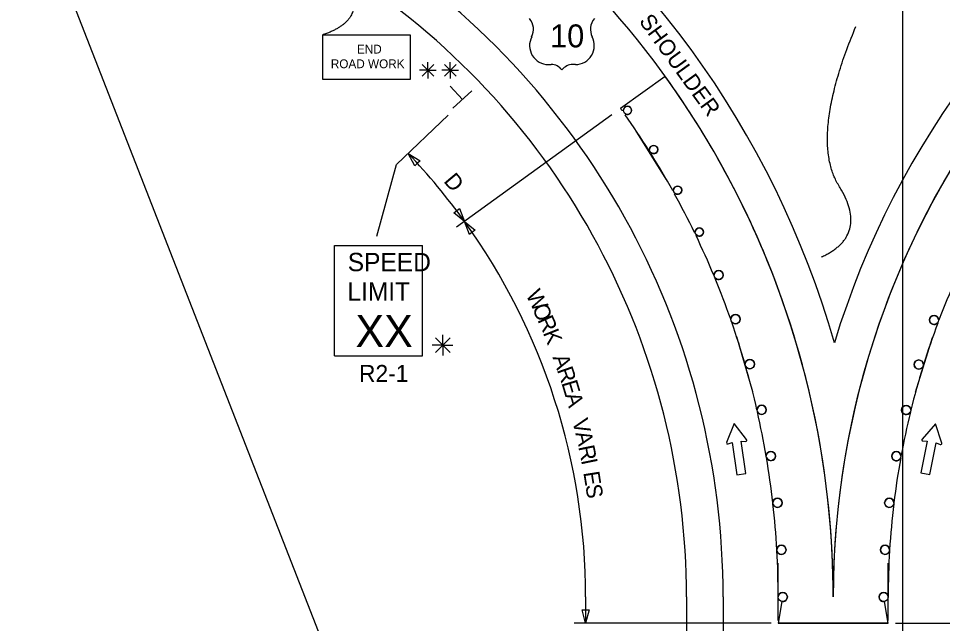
# Model space of a CAD drawing. Extents: x 16512 to 19512, y 5761 to 6974.
# Drawn here: x 16595 to 16998.2, y 6469 to 6732.7 of the extents above; entities that cross this region are included whole.
import ezdxf

# ---------------------------------------------------------------- set-up
doc = ezdxf.new("R2010")
doc.units = 0
for name, color, linetype in [('ALI_LEGAL_EX', 7, 'Continuous'), ('MT_SCRATCH_LEVEL_A', 7, 'Continuous'), ('PAVT_EDGE_EX', 7, 'Continuous'), ('TRAFFIC_SIGNS_PR', 7, 'Continuous'), ('TYPICAL_EX', 7, 'Continuous'), ('TYPICAL_TEXT_DIMEN_PR', 7, 'Continuous')]:
    doc.layers.add(name, color=color, linetype=linetype)

msp = doc.modelspace()

# ---------------------------------------------------------------- linework, layer by layer
at = {"layer": 'ALI_LEGAL_EX'}
for p, q in [((16980.68, 6974.12), (16980.68, 6155.98)), ((16980.68, 6922.21), (16980.68, 6058.3)), ((16594.98, 6800.51), (16817, 6232.14))]:
    msp.add_line(p, q, dxfattribs=at)
for points in [[(16877.62, 6662.6), (16864.4, 6683.82)], [(16915.36, 6569.9), (16908.35, 6593.9)], [(16986.38, 6569.82), (16993.83, 6593.69)], [(16926.45, 6470.33), (16926.45, 6495.33)], [(16974.45, 6470.33), (16974.45, 6495.33)]]:
    msp.add_lwpolyline(points, dxfattribs=at)
at = {"layer": 'MT_SCRATCH_LEVEL_A'}
for p, q in [((16974.45, 6469.09), (16926.45, 6469.09)), ((16926.45, 6469.09), (16974.45, 6469.09)), ((16974.45, 6469.09), (16926.45, 6469.09)), ((16974.24, 6469.09), (16974.45, 6469.3))]:
    msp.add_line(p, q, dxfattribs=at)
for points in [[(16877.19, 6707.43), (16857.72, 6693.39)], [(16858.22, 6692.7), (16858.9, 6692.69)], [(16860.1, 6690.97), (16859.67, 6690.66)], [(16869.94, 6675.32), (16870.34, 6675.58)], [(16871.36, 6673.96), (16870.96, 6673.71)], [(16880.44, 6657.67), (16880.81, 6657.87)], [(16881.65, 6656.35), (16881.28, 6656.15)], [(16889.92, 6639.44), (16890.27, 6639.61)], [(16890.94, 6638.2), (16890.6, 6638.04)], [(16898.34, 6620.78), (16898.49, 6620.85)], [(16899.07, 6619.44), (16898.92, 6619.38)], [(16905.72, 6601.59), (16905.83, 6601.63)], [(16906.27, 6600.39), (16906.16, 6600.35)], [(16996.1, 6599.94), (16995.98, 6599.98)], [(16996.47, 6601.3), (16996.6, 6601.25)], [(16912.01, 6582.02), (16912.09, 6582.04)], [(16912.4, 6580.98), (16912.32, 6580.96)], [(16989.53, 6580.69), (16989.45, 6580.72)], [(16989.79, 6581.84), (16989.88, 6581.82)], [(16917.19, 6562.11), (16917.24, 6562.12)], [(16917.44, 6561.26), (16917.38, 6561.25)], [(16984.13, 6561.09), (16984.07, 6561.1)], [(16984.29, 6562.02), (16984.35, 6562.01)], [(16921.23, 6541.95), (16921.26, 6541.95)], [(16921.37, 6541.3), (16921.34, 6541.29)], [(16979.9, 6541.2), (16979.87, 6541.21)], [(16979.99, 6541.91), (16980.03, 6541.9)], [(16924.12, 6521.59), (16924.14, 6521.59)], [(16924.19, 6521.14), (16924.17, 6521.14)], [(16976.88, 6521.1), (16976.86, 6521.1)], [(16976.91, 6521.57), (16976.93, 6521.57)], [(16925.87, 6501.09), (16925.87, 6501.09)], [(16925.88, 6500.87), (16925.88, 6500.87)], [(16975.05, 6500.85), (16975.05, 6500.85)], [(16975.06, 6501.09), (16975.07, 6501.09)], [(16926.45, 6480.53), (16926.45, 6480.53)], [(16974.44, 6480.53), (16974.45, 6480.53)], [(16928.11, 6478.56), (16926.45, 6469.09), (16974.45, 6469.09), (16972.78, 6478.56)]]:
    msp.add_lwpolyline(points, dxfattribs=at)
for centre, radius, start, end in [((16562.45, 6480.53), 388, 22.8554, 35.7873), ((17314.45, 6480.53), 364, 141.7598, 180), ((16562.45, 6480.53), 364, 35.6537, 35.7873), ((16860.7, 6692.67), 1.8, 0, 179.0978), ((16562.45, 6480.53), 364, 32.3536, 35.2603), ((16860.7, 6692.67), 1.8, 250.5205, 0), ((16872.14, 6675.58), 1.8, 0, 180), ((16562.45, 6480.53), 364, 29.1198, 32.0533), ((16872.14, 6675.58), 1.8, 244.1065, 0), ((16882.61, 6657.87), 1.8, 0, 180), ((16882.61, 6657.87), 1.8, 237.6934, 0), ((16562.45, 6480.53), 364, 25.8855, 28.8467), ((16892.07, 6639.61), 1.8, 0, 180), ((16562.45, 6480.53), 364, 22.663, 25.6406), ((16892.07, 6639.61), 1.8, 231.2811, 0), ((16562.45, 6480.53), 388, 0, 22.8554), ((16900.49, 6620.85), 2, 0, 180), ((16900.49, 6620.85), 2, 224.8459, 0), ((16562.45, 6480.53), 364, 19.4261, 22.4229), ((17314.45, 6480.53), 340, 156.0121, 159.2032), ((16907.83, 6601.63), 2, 0, 180), ((16562.45, 6480.53), 364, 16.189, 19.219), ((16907.83, 6601.63), 2, 218.4379, 0), ((16994.47, 6601.3), 2, 0, 180), ((16994.47, 6601.3), 2, 180, 318.8797), ((17314.45, 6480.53), 340, 159.4399, 162.6687), ((16914.09, 6582.04), 2, 0, 180), ((16987.79, 6581.84), 2, 0, 180), ((16562.45, 6480.53), 364, 12.9515, 16.0153), ((16914.09, 6582.04), 2, 212.0306, 0), ((17314.45, 6480.53), 340, 162.8672, 166.1345), ((16987.79, 6581.84), 2, 180, 325.7344), ((16919.24, 6562.13), 2, 0, 180), ((16982.29, 6562.02), 2, 0, 180), ((16562.45, 6480.53), 364, 9.7138, 12.8119), ((16919.24, 6562.13), 2, 205.6238, 0), ((17314.45, 6480.53), 340, 166.2942, 169.6006), ((16982.29, 6562.02), 2, 180, 332.5884), ((16923.26, 6541.95), 2, 0, 180), ((16978, 6541.91), 2, 0, 180), ((16562.45, 6480.53), 364, 6.476, 9.6087), ((16923.26, 6541.95), 2, 199.2175, 0), ((16978, 6541.91), 2, 180, 339.4418), ((17314.45, 6480.53), 340, 169.7209, 173.067), ((16926.14, 6521.59), 2, 0, 180), ((16974.91, 6521.57), 2, 0, 180), ((16562.45, 6480.53), 364, 3.238, 6.4057), ((16926.14, 6521.59), 2, 192.8115, 0), ((16974.91, 6521.57), 2, 180, 346.2947), ((17314.45, 6480.53), 340, 173.1474, 176.5334), ((16927.87, 6501.09), 2, 0, 180), ((16927.87, 6501.09), 2, 186.4057, 0), ((16562.45, 6480.53), 364, 0, 3.2028), ((16973.06, 6501.09), 2, 0, 180), ((16973.06, 6501.09), 2, 180, 353.1474), ((17314.45, 6480.53), 340, 176.5737, 180), ((16928.45, 6480.53), 2, 0, 180), ((16928.45, 6480.53), 2, 260.0595, 0), ((16972.44, 6480.53), 2, 0, 180), ((16972.44, 6480.53), 2, 180, 279.941)]:
    msp.add_arc(centre, radius, start, end, dxfattribs=at)
at = {"layer": 'PAVT_EDGE_EX'}
for p, q in [((16886.45, 6480.53), (16886.45, 6125.9)), ((16902.45, 6480.53), (16902.45, 6125.9))]:
    msp.add_line(p, q, dxfattribs=at)
for centre, radius, start, end in [((16562.45, 6480.53), 404, 15.917, 56.5037), ((16562.45, 6480.53), 388, 0, 56.5037), ((17314.45, 6480.53), 380, 121.9327, 163.0483), ((17314.45, 6480.53), 364, 121.9327, 180), ((16562.45, 6480.53), 340, 0, 56.5037), ((16562.45, 6480.53), 324, 0, 56.5037)]:
    msp.add_arc(centre, radius, start, end, dxfattribs=at)
at = {"layer": 'TRAFFIC_SIGNS_PR'}
for p, q in [((16732.88, 6633.68), (16771.28, 6633.68)), ((16732.88, 6585.68), (16732.88, 6633.68)), ((16771.28, 6585.68), (16771.28, 6633.68)), ((16732.88, 6585.68), (16771.28, 6585.68))]:
    msp.add_line(p, q, dxfattribs=at)
msp.add_lwpolyline([(16727.65, 6706.29), (16766.05, 6706.29), (16766.05, 6725.49), (16727.65, 6725.49)], close=True, dxfattribs=at)
for centre, radius in [((16860.7, 6692.67), 1.8), ((16872.14, 6675.58), 1.8), ((16882.61, 6657.87), 1.8), ((16892.07, 6639.61), 1.8), ((16900.49, 6620.85), 2), ((16907.83, 6601.63), 2), ((16994.47, 6601.3), 2), ((16914.09, 6582.04), 2), ((16987.79, 6581.84), 2), ((16919.24, 6562.13), 2), ((16982.29, 6562.02), 2), ((16923.26, 6541.95), 2), ((16978, 6541.91), 2), ((16926.14, 6521.59), 2), ((16974.91, 6521.57), 2), ((16927.87, 6501.09), 2), ((16973.06, 6501.09), 2), ((16928.45, 6480.53), 2), ((16972.44, 6480.53), 2)]:
    msp.add_circle(centre, radius, dxfattribs=at)
at = {"layer": 'TYPICAL_EX'}
for p, q in [((16826.2, 6712.63), (16827.38, 6712.63)), ((16838.01, 6712.63), (16836.83, 6712.63))]:
    msp.add_line(p, q, dxfattribs=at)
for centre, radius, start, end in [((16812.37, 6727.97), 7.31, 333.0977, 40.1936), ((16851.84, 6727.97), 7.31, 139.8064, 206.9023), ((16826.22, 6720.87), 8.24, 152.6698, 269.9013), ((16837.99, 6720.87), 8.24, 270.0987, 27.3302), ((16827.4, 6706.72), 5.91, 37.1038, 90.1385), ((16836.82, 6706.72), 5.91, 89.8615, 142.8962)]:
    msp.add_arc(centre, radius, start, end, dxfattribs=at)
at = {"layer": 'TYPICAL_TEXT_DIMEN_PR'}
for p, q in [((16773.6, 6710.11), (16773.6, 6713.68)), ((16783.34, 6710.11), (16783.34, 6713.68)), ((16773.6, 6710.11), (16769.97, 6710.11)), ((16771.05, 6712.66), (16776.15, 6707.56)), ((16776.15, 6712.66), (16771.05, 6707.56)), ((16773.6, 6710.11), (16776.15, 6710.11)), ((16773.6, 6710.11), (16777.18, 6710.11)), ((16773.6, 6710.11), (16773.6, 6706.51)), ((16783.34, 6710.11), (16779.72, 6710.11)), ((16780.79, 6712.66), (16785.89, 6707.56)), ((16785.89, 6712.66), (16780.79, 6707.56)), ((16783.34, 6710.11), (16785.89, 6710.11)), ((16783.34, 6710.11), (16786.92, 6710.11)), ((16783.34, 6710.11), (16783.34, 6706.51)), ((16788.67, 6697.41), (16783.39, 6703.13)), ((16792.81, 6701.23), (16784.54, 6693.59)), ((16782.47, 6690.48), (16759.98, 6669.02)), ((16853.94, 6690.66), (16786.14, 6641.79)), ((16767.93, 6668.5), (16765.02, 6673.83)), ((16765.02, 6673.83), (16770.2, 6670.67)), ((16751.28, 6637.84), (16759.98, 6669.02)), ((16769.07, 6669.59), (16767.93, 6668.5)), ((16770.2, 6670.67), (16769.07, 6669.59)), ((16784.92, 6648.05), (16786.2, 6648.96)), ((16786.2, 6648.96), (16787.47, 6649.88)), ((16787.47, 6649.88), (16789.62, 6644.21)), ((16789.62, 6644.21), (16784.92, 6648.05)), ((16791.72, 6638.58), (16789.56, 6644.26)), ((16789.56, 6644.26), (16794.27, 6640.42)), ((16794.27, 6640.42), (16792.99, 6639.5)), ((16792.99, 6639.5), (16791.72, 6638.58)), ((16783.26, 6593.48), (16776.88, 6587.11)), ((16776.89, 6593.48), (16783.26, 6587.11)), ((16780.07, 6590.29), (16780.07, 6594.75)), ((16780.07, 6590.29), (16775.54, 6590.29)), ((16780.07, 6590.29), (16783.26, 6590.29)), ((16780.07, 6590.29), (16784.55, 6590.29)), ((16780.07, 6590.29), (16780.07, 6585.79)), ((16907.2, 6556.15), (16903.97, 6547.88)), ((16912.69, 6549.15), (16907.2, 6556.15)), ((16995.04, 6556.07), (16989.21, 6549.38)), ((16997.84, 6547.63), (16995.04, 6556.07)), ((16904.59, 6547.23), (16906.41, 6547.83)), ((16906.41, 6547.83), (16908.45, 6533.84)), ((16912.4, 6534.42), (16910.36, 6548.41)), ((16910.36, 6548.41), (16912.29, 6548.35)), ((16991.49, 6548.51), (16988.68, 6534.65)), ((16989.57, 6548.56), (16991.49, 6548.51)), ((16992.59, 6533.86), (16995.41, 6547.72)), ((16995.41, 6547.72), (16997.2, 6547.01)), ((16908.45, 6533.84), (16912.4, 6534.42)), ((16988.68, 6534.65), (16992.59, 6533.86)), ((16842.45, 6480.53), (16842.45, 6469.09)), ((16842.45, 6480.53), (16842.45, 6469.09)), ((16842.45, 6469.09), (16840.88, 6474.95)), ((16840.88, 6474.95), (16842.45, 6474.95)), ((16842.45, 6474.95), (16844.02, 6474.95)), ((16844.02, 6474.95), (16842.45, 6469.09)), ((16923.32, 6469.09), (16837.45, 6469.09)), ((16977.64, 6469.09), (17063.45, 6469.09))]:
    msp.add_line(p, q, dxfattribs=at)
for centre, radius, start, end in [((16562.45, 6480.53), 280, 35.772, 43.6576), ((16562.45, 6480.53), 280, 0, 35.772), ((16904.44, 6547.7), 0.494, 158.71, 288.249), ((16912.29, 6548.85), 0.494, 268.3214, 38.0583), ((16989.59, 6549.06), 0.494, 138.9563, 268.4952), ((16997.37, 6547.48), 0.494, 248.5676, 18.3045)]:
    msp.add_arc(centre, radius, start, end, dxfattribs=at)
for points in [[(16742.2, 6749.78), (16742.81, 6740.39), (16738.12, 6729.17), (16727.65, 6725.49)], [(16945.34, 6628.75), (16966.33, 6638.37), (16939.94, 6680.45), (16960.33, 6729.14)]]:
    msp.add_open_spline(points, degree=2, dxfattribs=at)

# ---------------------------------------------------------------- texts
at = {"layer": 'TRAFFIC_SIGNS_PR'}
for s, height, p in [('END', 3.831, (16742.65, 6717.42)), ('ROAD WORK', 3.831, (16731.26, 6711.03)), ('SPEED', 8, (16738.65, 6622.54)), ('LIMIT', 8, (16738.49, 6609.74)), ('XX', 14.031, (16742, 6589.44)), ('R2-1', 7.44, (16743.56, 6574.24))]:
    msp.add_text(s, height=height, dxfattribs=at).set_placement(p)
at = {"layer": 'TYPICAL_EX'}
msp.add_text('10', height=10, dxfattribs=at).set_placement((16826.95, 6720.11))
at = {"layer": 'TYPICAL_TEXT_DIMEN_PR'}
for s, rotation, p in [('SHOULDER', 305.9489, (16865.49, 6731.47)), ('D', 310, (16780.2, 6661.69)), ('W', 296.9052, (16816.15, 6612.34)), ('O', 294.3428, (16818.92, 6606.56)), ('R', 294.3428, (16821.29, 6601.3)), ('K', 291.7804, (16823.71, 6595.69)), ('A', 289.218, (16827.93, 6584.98)), ('R', 289.218, (16829.82, 6579.54)), ('E', 286.6556, (16831.79, 6573.88)), ('A', 286.6556, (16833.38, 6568.56)), ('V', 284.0932, (16836.52, 6557.36)), ('A', 284.0932, (16837.88, 6551.97)), ('R', 281.5308, (16839.21, 6546.04)), ('I', 281.5308, (16840.42, 6540.15)), ('E', 278.9684, (16841.42, 6534.81)), ('S', 278.9684, (16842.3, 6529.22))]:
    msp.add_text(s, height=7, rotation=rotation, dxfattribs=at).set_placement(p)

doc.saveas('drawing.dxf')
